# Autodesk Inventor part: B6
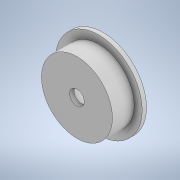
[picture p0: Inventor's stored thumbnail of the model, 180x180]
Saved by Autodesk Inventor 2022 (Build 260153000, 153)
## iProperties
Created: 2024-12
Part Number: B6
Material: 一般
Document SubType Name: Modeling
Designer: jsat7
Density: 1 g/cm^3
Appearance: 既定
Author: jsat7
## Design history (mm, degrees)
sketch "スケッチ1"
  geometry: C1 r 2.45 at (0, 0); 1 further point
  constraints: 1 centre point, 1 coincident
  dimensions: "d0" = 4.9 diameter of C1
extrude "押し出し1" new body sketch "スケッチ1" distance "d1" = 1.5; taper "d2" = 0 deg
sketch "スケッチ2"
  geometry: C1 r 3 at (0, 0); 1 further point
  constraints: 1 centre point, 1 coincident
  dimensions: "d3" = 6 diameter of C1
extrude "押し出し2" join sketch "スケッチ2" distance "d4" = 0.3; taper "d5" = 0 deg
sketch "スケッチ3"
  geometry: C1 r 1.5 at (0, 0); 1 further point
  constraints: 1 centre point, 1 coincident
  dimensions: "d6" = 3 diameter of C1
extrude "押し出し3" cut sketch "スケッチ3" distance "d7" = 1.5; taper "d8" = 0 deg
sketch "スケッチ4"
  geometry: C1 r 0.5 at (0, 0); 1 further point
  constraints: 1 centre point, 1 coincident
  dimensions: "d9" = 1 diameter of C1
extrude "押し出し4" cut sketch "スケッチ4" distance "d10" = 0.3; taper "d11" = 0 deg
node "ソリッド1"
